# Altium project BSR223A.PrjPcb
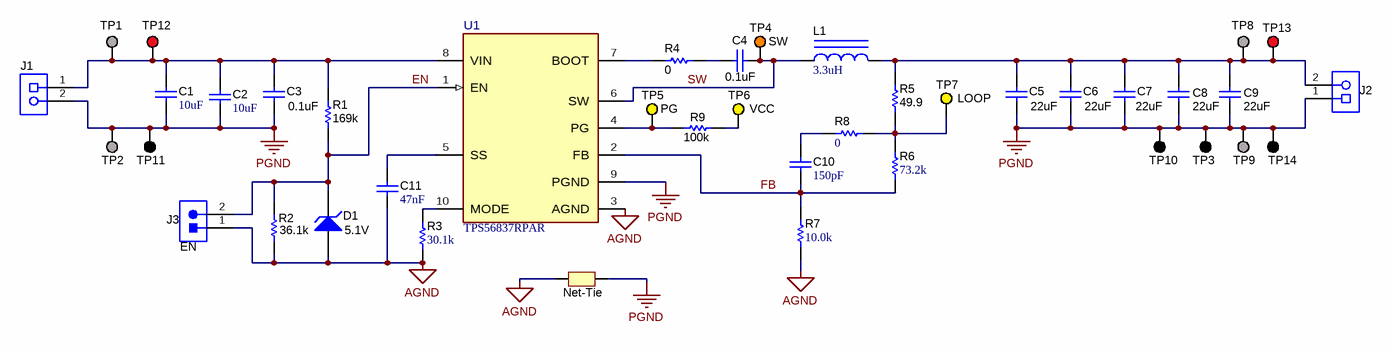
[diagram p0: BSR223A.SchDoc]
CopyrightYear: 2022; PCB_Layout: Miranda Gu; PCB_Rev: A; PRJ_Customer: Public Release; PRJ_Engineer: Miranda Gu; PRJ_Number: BSR223; PRJ_Title: TPS56837EVM; SCH_Rev: A; TechSupport: http://www.ti.com/support; TID: N/A
2 sheets, 58 parts. Net scope: global (net labels, ports and power ports of the same name join across sheets).
Board file: BSR223A.PcbDoc
Sheets:
  BSR223A.SchDoc
  BSR223A_Hardware.SchDoc

## Sheet BSR223A.SchDoc
size 431 x 279 mm; Date: Not shown in title block; ApprovedBy: Not shown in title block; CheckedBy: Not shown in title block; Author: Not shown in title block; CompanyName: Not shown in title block; Organization: Not shown in title block; Address1: Not shown in title block; Address2: Not shown in title block; Address3: Not shown in title block; Address4: Not shown in title block; DocumentNumber: 1; Revision: Use project parameter SCH_Rev; SheetNumber: 1; SheetTotal: 2; PageSetup: Record=PageOptions¦CenterHorizontal=True¦CenterVertical=True¦PrintScale=1.00¦XCorrection=1.00¦YCorrection=1.00¦PrintKind=0¦BorderSize=5000000¦LeftOffset=0¦BottomOffset=0¦Orientation=2¦PaperLength=1000¦PaperWidth=1000¦Scale=100¦PaperSource=15¦PrintQuality=600¦MediaType=1¦DitherType=10¦PaperKind=Letter¦PrintScaleMode=1

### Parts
C1  ValueDisplayed: 10uF  [1210_270]  (hidden comment: GRM32ER7YA106KA12L)
C2  ValueDisplayed: 10uF  [1210_270]  (hidden comment: GRM32ER7YA106KA12L)
C3  ValueDisplayed: 0.1uF  [0603]  (hidden comment: 885012206095)
C4  ValueDisplayed: 0.1uF  [0603]  (hidden comment: 885012206095)
C5  ValueDisplayed: 22uF  [1210_270]  (hidden comment: GRM32ER71E226KE15L)
C6  ValueDisplayed: 22uF  [1210_270]  (hidden comment: GRM32ER71E226KE15L)
C7  ValueDisplayed: 22uF  [1210_270]  (hidden comment: GRM32ER71E226KE15L)
C8  ValueDisplayed: 22uF  [1210_270]  (hidden comment: GRM32ER71E226KE15L)
C9  ValueDisplayed: 22uF  [1210_270]  (hidden comment: GRM32ER71E226KE15L)
C10  ValueDisplayed: 150pF  [0603]  (hidden comment: GRM1885C1H151JA01D)
C11  Cap_F: 47nF  [0603]  (hidden comment: C1608X7R1H473K080AA)
D1  value 5.1V  [SOD-323]  (hidden comment: MMSZ5231BS-7-F)
J1  ED120/2DS  [On-Shore_ED120_2DS]  (value not drawn)
J2  ED120/2DS  [On-Shore_ED120_2DS]  (value not drawn)
J3  EN  [TSW-102-07-X-S]
L1  ValueDisplayed: 3.3uH  [WE-HC6]  (hidden comment: 744325330)
NT1  Net-Tie  [NetTie_0603]  (net tie, no BOM)
R1  ValueDisplayed: 169k  [0603]  (hidden comment: RT0603BRD07169KL)
R2  ValueDisplayed: 36.1k  [0603]  (hidden comment: RT0603BRD0736K1L)
R3  ValueDisplayed: 30.1k  [0603]  (hidden comment: RT0603DRE0730K1L)
R4  ValueDisplayed: 0  [0603]  (hidden comment: CRCW06030000Z0EA)
R5  ValueDisplayed: 49.9  [0603]  (hidden comment: RT0603DRE0749R9L)
R6  ValueDisplayed: 73.2k  [0603]  (hidden comment: RT0603DRE0773K2L)
R7  ValueDisplayed: 10.0k  [0603]  (hidden comment: RT0603DRE0710KL)
R8  ValueDisplayed: 0  [0603]  (hidden comment: RC0603JR-070RL)
R9  ValueDisplayed: 100k  [0603]  (hidden comment: CRCW0603100KFKEA)
TP1  VIN  [Keystone1502-2]  (value not drawn)
TP2  PGND  [Keystone1502-2]  (value not drawn)
TP3  PGND  [Keystone5011]  (value not drawn)
TP4  SW  [Keystone5013]
TP5  PG  [Keystone5014]
TP6  VCC  [Keystone5014]
TP7  LOOP  [Keystone5014]
TP8  VOUT  [Keystone1502-2]  (value not drawn)
TP9  PGND  [Keystone1502-2]  (value not drawn)
TP10  PGND  [Keystone5011]  (value not drawn)
TP11  PGND_SNS  [Keystone5011]  (value not drawn)
TP12  VIN_SNS  [Keystone5010]  (value not drawn)
TP13  VOUT_SNS  [Keystone5010]  (value not drawn)
TP14  PGND_SNS  [Keystone5011]  (value not drawn)
U1  TPS56837RPAR  [RPA0010A-MFG]

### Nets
AGND: C11.2 D1.2(A) J3.1 NT1.1 R2.1 R3.1 R7.2 U1.3(AGND)
PGND: C1.1 C2.1 C3.1 C5.2 C6.2 C7.2 C8.2 C9.2 J1.2 J2.1 NT1.2 TP2.1 TP3.1 TP9.1 TP10.1 TP11.1 TP14.1 U1.9(PGND)
EN: D1.1(K) J3.2 R1.1 R2.2 U1.1(EN)
FB: C10.2 R6.1 R7.1 U1.2(FB)
SW: C4.1 L1.1 TP4.1 U1.6(SW)
NetC1_2: C1.2 C2.2 C3.2 J1.1 R1.2 TP1.1 TP12.1 U1.8(VIN)
NetC4_2: C4.2 R4.2
NetC5_1: C5.1 C6.1 C7.1 C8.1 C9.1 J2.2 L1.2 R5.2 TP8.1 TP13.1
NetC10_1: C10.1 R8.1
NetC11_1: C11.1 U1.5(SS)
NetR3_2: R3.2 U1.10(MODE)
NetR4_1: R4.1 U1.7(BOOT)
NetR5_1: R5.1 R6.2 R8.2 TP7.1
NetR9_1: R9.1 TP5.1 U1.4(PG)
NetR9_2: R9.2 TP6.1

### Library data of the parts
C1 C2 = CMP-0009233-2: CAP, CERM, 10 uF, 35 V, +/- 10%, X7R, 1210; Manufacturer: MuRata; SizeZ_mm: 2.7; Value: 10uF; Value2: 35V; Cap_Case: 1210; Cap_F: 10µF; Value1: Unknown; TaMin_C: -55°C; U/M: EA; SizeArea_mm2: 8; TaMax_C: 125°C; AEC Category: Q200; SizeX_mm: 3.2; SizeY_mm: 2.5; Polarized: N; SizeAreaWB_mm2: 14.7
C3 C4 = CMP-0006837-4: CAP, CERM, 0.1 uF, 50 V, +/- 10%, X7R, 0603; Manufacturer: Wurth Elektronik; TaMin_C: -55°C; Polarized: N; SizeAreaWB_mm2: 4.68; Value1: Unknown; U/M: EA; Value: 0.1uF; TaMax_C: 125°C; SizeZ_mm: 1; SizeX_mm: 1.6; SizeY_mm: 0.8; Value2: 50V; SizeArea_mm2: 1.28; CompType: Capacitor; Cap_F: 100nF; AEC Category: Q200
C5-C9 = CMP-0009224-2: CAP, CERM, 22 uF, 25 V, +/- 10%, X7R, 1210; Manufacturer: MuRata; TaMin_C: -55°C; Polarized: N; SizeAreaWB_mm2: 14.7; Value1: Unknown; U/M: EA; Value: 22uF; TaMax_C: 125°C; SizeZ_mm: 2.7; SizeX_mm: 3.2; SizeY_mm: 2.5; Cap_Case: 1210; Value2: 25V; SizeArea_mm2: 8; CompType: Capacitor; Cap_F: 22µF; AEC Category: Q200
C10 = CMP-0007185-2: CAP, CERM, 150 pF, 50 V, +/- 5%, C0G/NP0, 0603; Manufacturer: MuRata; TaMin_C: -55°C; Polarized: N; SizeAreaWB_mm2: 4.68; Value1: Unknown; U/M: EA; Value: 150pF; TaMax_C: 125°C; SizeZ_mm: 1; SizeX_mm: 1.6; SizeY_mm: 0.8; Value2: 50V; SizeArea_mm2: 1.28; AEC Category: Q200
C11 = CMP-0007049-4: CAP, CERM, 0.047 uF, 50 V, +/- 10%, X7R, 0603; Manufacturer: TDK; TaMin_C: -55°C; ESR_ohm: 49.007m; Polarized: N; SizeAreaWB_mm2: 4.68; Value1: 0.049007 ohm; U/M: EA; TaMax_C: 125°C; SizeZ_mm: 1; SizeX_mm: 1.6; SizeY_mm: 0.8; Value2: 50V; SizeArea_mm2: 1.28; IRMS_A: 767.528mA; AEC Category: Q200
D1 = CMP-0005854-3: Diode, Zener, 5.1 V, 200 mW, SOD-323; Manufacturer: Diodes Inc.; SizeX_mm: 2.7; SizeZ_mm: 1; RJA_CperW: 350; Power_W: 200mW; SizeAreaWB_mm2: 8.695; AEC Category: Q101; Value1: 0.2W; SizeArea_mm2: 3.645; SizeY_mm: 1.35
J1 J2 = CMP-0074910-1: Terminal Block, 5.08 mm, 2x1, Brass, TH; Manufacturer: On-Shore Technology; Cert_VDE: Y; CNHeader: False; Current_A: 15A; Green_Lifecycle: Not Set; Shrouded: N; Gender: Female; Green_REACh: Incomplete; Voltage_V: 300V; Row_Count: 1; Pitch_mm: 5.08; CT: True
J3 = CMP-0075405-1: Header, 100mil, 2x1, Gold, TH; PartNumber: TSW-102-07-G-S; Manufacturer: Samtec; Pitch_mm: 2.54; Cert_VDE: N; Gender: Male; Cert_CSA: Y; Voltage_V: 550V; Green_REACh: Passed; Current_A: 6.3A; CT: False; Green_Lifecycle: Active; Row_Count: 1; CNHeader: True
L1 = CMP-0063965-1: Inductor, Shielded Drum Core, Superflux, 3.3 uH, 12 A, 0.0059 ohm, SMD; Manufacturer: Wurth Elektronik; Isat: 15A @ 30% inductance drop; Irms: 12A @ 50C rise; Green_Lifecycle: Active; SizeAreaWB_mm2: 158.6; DCR_ohm: 5.9m; Green_REACh: Passed; Value: 3.3uH; Imax_A: 12A; SizeZ_mm: 5; SizeX_mm: 11; SizeY_mm: 10.2; SizeArea_mm2: 112.2; Ind_H: 3.3µH; AEC Category: Q200
NT1 = CMP-0078142-1: Single point connection between nets.
R1 = CMP-0023796-3: RES, 169 k, 0.1%, 0.1 W, 0603; Manufacturer: Yageo America; Power_W: 100mW; TempCo: 25 ppm/C; U/M: EA; Value: 169k; EIA_Code: E192; SizeX_mm: 1.6; SizeY_mm: 0.8; SizeZ_mm: 1; Value2: 0.1W; SizeArea_mm2: 1.28; CompType: Resistor; VDC_V: 75V; AEC Category: Q200
R2 = CMP-0024154-3: RES, 36.1 k, 0.1%, 0.1 W, 0603; Manufacturer: Yageo America; Power_W: 100mW; TempCo: 25 ppm/C; Value_Code: 36k1; U/M: EA; Value: 36.1k; EIA_Code: E192; SizeX_mm: 1.6; SizeY_mm: 0.8; SizeZ_mm: 1; Value2: 0.1W; SizeArea_mm2: 1.28; CompType: Resistor; VDC_V: 75V; AEC Category: Q200
R3 = CMP-0025121-3: RES, 30.1 k, 0.5%, 0.1 W, 0603; Manufacturer: Yageo America; Power_W: 100mW; TempCo: 50 ppm/C; Value_Code: 30k1; U/M: EA; Value: 30.1k; EIA_Code: E192; SizeX_mm: 1.6; SizeY_mm: 0.8; SizeZ_mm: 1; Value2: 0.1W; SizeArea_mm2: 1.28; VDC_V: 75V; AEC Category: Q200
R4 = CRCW06030000Z0EA: RES, 0, 5%, 0.1 W, 0603; Manufacturer: Vishay-Dale; CompType: Resistor; Value: 0; Value_Code: 0000; Tolerance_%: 5; Power_W: 0.1; Value2: 0.1W; VDC_V: 75; TempCo: 200 ppm/C; SizeArea_mm2: 1.28; SizeX_mm: 1.6; SizeY_mm: 0.8; SizeZ_mm: 1; EIA_Code: E24; U/M: EA; AEC Category: Q200; Green_Lifecycle: Active; Green_REACh: Passed
R5 = CMP-0025334-3: RES, 49.9, 0.5%, 0.1 W, 0603; Manufacturer: Yageo America; Power_W: 100mW; TempCo: 50 ppm/C; Value_Code: 49R9; U/M: EA; Value: 49.9; EIA_Code: E192; SizeX_mm: 1.6; SizeY_mm: 0.8; SizeZ_mm: 1; Value2: 0.1W; SizeArea_mm2: 1.28; CompType: Resistor; VDC_V: 75V; AEC Category: Q200
R6 = CMP-0025549-3: RES, 73.2 k, 0.5%, 0.1 W, 0603; Manufacturer: Yageo America; Power_W: 100mW; TempCo: 50 ppm/C; Value_Code: 73k2; U/M: EA; Value: 73.2k; EIA_Code: E192; SizeX_mm: 1.6; SizeY_mm: 0.8; SizeZ_mm: 1; Value2: 0.1W; SizeArea_mm2: 1.28; VDC_V: 75V; AEC Category: Q200
R7 = CMP-0024586-3: RES, 10.0 k, 0.5%, 0.1 W, 0603; Manufacturer: Yageo America; Power_W: 100mW; TempCo: 50 ppm/C; Value_Code: 10k0; U/M: EA; Value: 10.0k; EIA_Code: E192; Res_ohm: 10k; SizeX_mm: 1.6; SizeY_mm: 0.8; SizeZ_mm: 1; Value2: 0.1W; SizeArea_mm2: 1.28; VDC_V: 75V; AEC Category: Q200
R8 = CMP-0025885-5: RES, 0, 5%, 0.1 W, 0603; Manufacturer: Yageo; Power_W: 100mW; TempCo: 200 ppm/C; Value_Code: 0000; Value: 0; EIA_Code: E24; SizeX_mm: 1.6; SizeZ_mm: 1; Value2: 0.1W; SizeArea_mm2: 1.28; AEC Qualified: N; VDC_V: 75V; AEC Category: Q200; SizeY_mm: 0.8; SizeAreaWB_mm2: 4.68
R9 = CMP-0021990-3: RES, 100 k, 1%, 0.1 W, 0603; Manufacturer: Vishay-Dale; Power_W: 100mW; TempCo: 100 ppm/C; U/M: EA; Value: 100k; EIA_Code: E96; SizeX_mm: 1.6; SizeY_mm: 0.8; SizeZ_mm: 1; Value2: 0.1W; SizeArea_mm2: 1.28; VDC_V: 75V; AEC Category: Q200
TP1 TP2 TP8 TP9 = CMP-0055113-1: Terminal, Turret, TH, Double; PartNumber: 1502-2; Manufacturer: Keystone; CompType: Turret Terminal; CNHeader: FALSE; Green_Lifecycle: Active; Green_REACh: Passed
TP3 TP10 TP11 TP14 = CMP-0055148-1: Test Point, Multipurpose, Black, TH; Manufacturer: Keystone; PartNumber: 5011; CNHeader: FALSE; Green_Lifecycle: Active; Green_REACh: Passed; ContactFinish: Silver; CT: TRUE
TP4 = CMP-0055150-1: Test Point, Multipurpose, Orange, TH; Manufacturer: Keystone; PartNumber: 5013; CNHeader: FALSE; Green_Lifecycle: Active; Green_REACh: Passed; ContactFinish: Silver; CT: TRUE
TP5-TP7 = CMP-0055151-1: Test Point, Multipurpose, Yellow, TH; Manufacturer: Keystone; PartNumber: 5014; CNHeader: FALSE; Green_Lifecycle: Active; Green_REACh: Passed; ContactFinish: Silver; CT: TRUE
TP12 TP13 = CMP-0055147-1: Test Point, Multipurpose, Red, TH; Manufacturer: Keystone; PartNumber: 5010; CNHeader: FALSE; Green_Lifecycle: Active; Green_REACh: Passed; ContactFinish: Silver; CT: TRUE
U1 = CMP-0094944-4: 4.5-V to 28-V Input, 8-A Synchronous Buck Converter; Manufacturer: Texas Instruments; Max Duty Cycle: 98%; Output Type: AdjustableProgrammable; Number Of Outputs: 1; Nominal Supply Current: 70uA; Standoff Height: 0mm; Min Supply Voltage: 4.5V; Max Supply Voltage: 28V; Output Voltage: 0.6-13V; TJmax_C: +150°C; AEC Category: Q200; CompType: IC; AEC Qualified: No; SizeZ_mm: 1mm; Switching Frequency: 500/800/1200kHz

## Sheet BSR223A_Hardware.SchDoc
size 431 x 279 mm; Date: Not shown in title block; ApprovedBy: Not shown in title block; CheckedBy: Not shown in title block; Author: Not shown in title block; CompanyName: Not shown in title block; Organization: Not shown in title block; Address1: Not shown in title block; Address2: Not shown in title block; Address3: Not shown in title block; Address4: Not shown in title block; DocumentNumber: 1; Revision: Use project parameter SCH_Rev; SheetNumber: 2; SheetTotal: 2; PageSetup: Record=PageOptions¦CenterHorizontal=True¦CenterVertical=True¦PrintScale=1.00¦XCorrection=1.00¦YCorrection=1.00¦PrintKind=0¦BorderSize=5000000¦LeftOffset=0¦BottomOffset=0¦Orientation=2¦PaperLength=1000¦PaperWidth=1000¦Scale=100¦PaperSource=15¦PrintQuality=600¦MediaType=1¦DitherType=10¦PaperKind=Letter¦PrintScaleMode=1
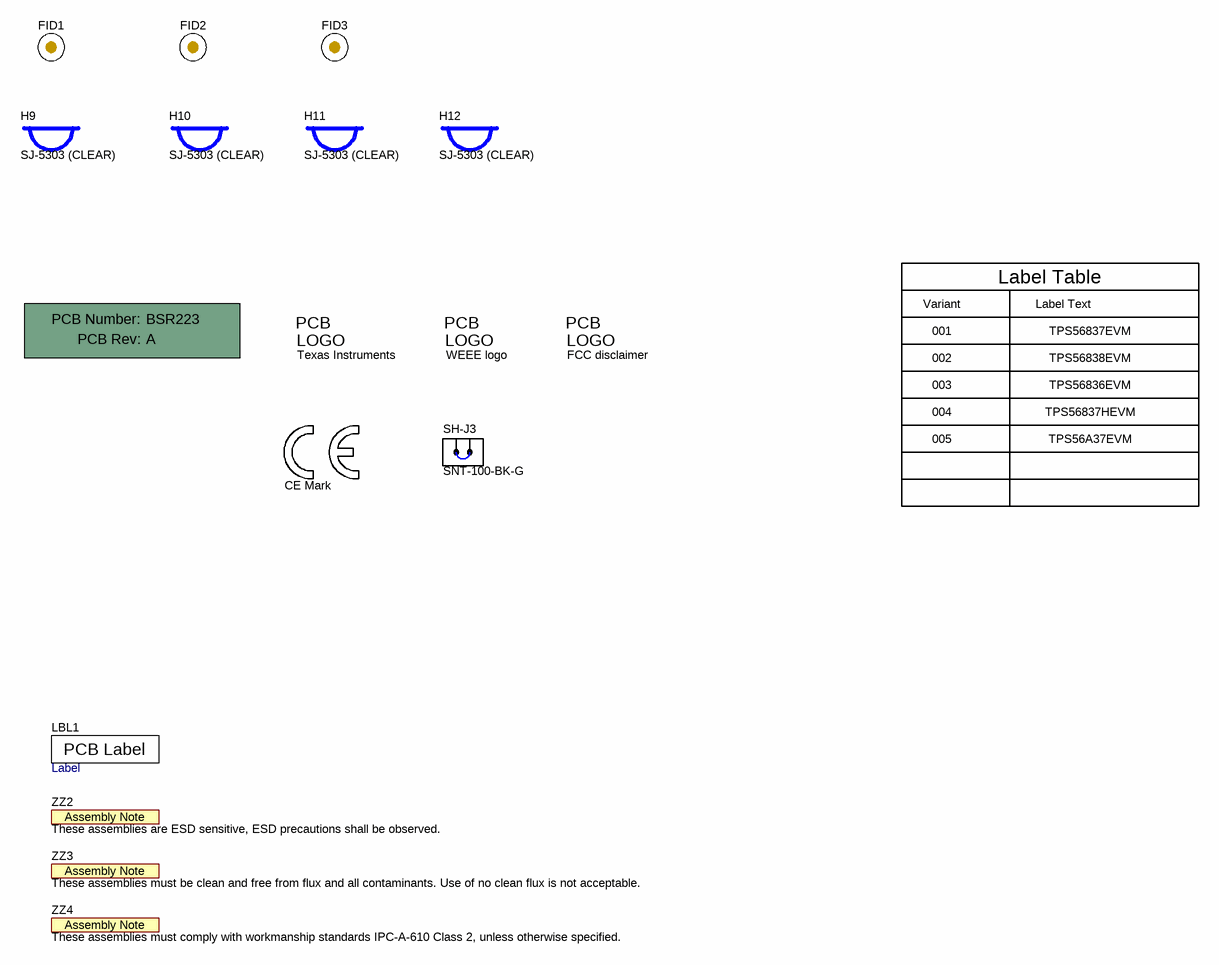
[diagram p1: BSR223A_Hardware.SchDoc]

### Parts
!PCB  Printed Circuit Board  (value not drawn)  (mechanical)
FID1  Fiducial  [Fiducial10-20]  (value not drawn)
FID2  Fiducial  [Fiducial10-20]  (value not drawn)
FID3  Fiducial  [Fiducial10-20]  (value not drawn)
H9  SJ-5303 (CLEAR)  [Bumpon_SJ5003Transparent]
H10  SJ-5303 (CLEAR)  [Bumpon_SJ5003Transparent]
H11  SJ-5303 (CLEAR)  [Bumpon_SJ5003Transparent]
H12  SJ-5303 (CLEAR)  [Bumpon_SJ5003Transparent]
LBL1  Label  [Label_1250x250]
Logo1  Texas Instruments  [TI_Stacked_Overlay_Small]  (no BOM)
Logo2  WEEE logo  [WEEE_Minimum]  (no BOM)
Logo3  FCC disclaimer  [FCC_disclaimer]  (no BOM)
Logo4  CE Mark  [CE_Mark_5mm]  (no BOM)
SH-J3  SNT-100-BK-G  [SNT-100-BK-G]
ZZ2  These assemblies are ESD sensitive, ESD precautions shall be observed.  [AssemblyNote]  (no BOM)
ZZ3  These assemblies must be clean and free from flux and all contaminants. Use of no clean flux is not acceptable.  [AssemblyNote]  (no BOM)
ZZ4  These assemblies must comply with workmanship standards IPC-A-610 Class 2, unless otherwise specified.  [AssemblyNote]  (no BOM)

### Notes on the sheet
- Variant
- Label Table
- Label Text
- 001
- 002
- TPS56837EVM
- TPS56838EVM
- 003
- 004
- 005
- TPS56836EVM
- TPS56837HEVM
- TPS56A37EVM

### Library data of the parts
!PCB = CMP-0003618-2: Manufacturer: Any; PartNumber: BSR223
FID1-FID3 = CMP-0077181-1: Fiducial mark.  There is nothing to buy or mount.
H9-H12 = SJ-5303 (CLEAR): Bumpon, Hemisphere, 0.44 X 0.20, Clear; Manufacturer: 3M; SymbolCreator: a0412235
LBL1 = CMP-0003624-1: Thermal Transfer Printable Labels, 1.250" W x 0.250" H - 10,000 per roll; Manufacturer: Brady; PartNumber: THT-13-457-10; Note: Size: 1.25" x 0.25"
Logo1 = CMP-0074838-1: Texas Instrument Corporate Signature; SymbolCreator: a0412235; Lib Reference: TI_Logo; Library Reference: Logo
Logo2 = CMP-0074769-1
Logo3 = CMP-0074847-1: FCC_disclaimer; Library Reference: Logo
Logo4 = CMP-0074844-1: SymbolCreator: a0412235
SH-J3 = CMP-0003623-3: Shunt, 100mil, Gold plated, Black; Manufacturer: Samtec; Alternate Manufacturer: 3M; Alternate PartNumber: 969102-0000-DA; Value: 1x2; Note: You can "mate" this to a header by matching the designator.  i.e. use SH-J3 for header J3
ZZ2 = CMP-0077236-1
ZZ3 = CMP-0077237-1
ZZ4 = CMP-0077238-1

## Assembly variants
001: not fitted C7 C8 C9 FID1 FID2 FID3
002: not fitted C7 C8 C9 FID1 FID2 FID3; alternate parts U1 -> CMP-0097668-2
003: not fitted C7 C8 C9 FID1 FID2 FID3; alternate parts U1 -> CMP-0097666-2
004: not fitted C9 FID1 FID2 FID3; alternate parts C8 -> CMP-0008667-2, C7 -> CMP-0008667-2, U1 -> CMP-0097667-2, L1 -> CMP-0064003-1, R7 -> CMP-0024811-3, R6 -> CMP-0023020-5, C10 -> CMP-0007171-4, C5 -> CMP-0008667-2, C6 -> CMP-0008667-2, R3 -> CMP-0025387-3
005: not fitted C7 C8 C9 FID1 FID2 FID3; alternate parts U1 -> CMP-0047168-2, R3 -> CMP-0025387-3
